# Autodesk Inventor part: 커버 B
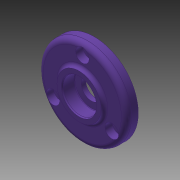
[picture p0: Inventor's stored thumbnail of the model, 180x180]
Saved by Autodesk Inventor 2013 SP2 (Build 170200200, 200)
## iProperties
Created: 2020-04
Part Number: 커버 B
Material: 알루미늄 6061
Document SubType Name: Modeling
Designer: mduedu
Density: 2.71 g/cm^3
Mass: 35.0669 g
Surface Area: 63.5386 cm^2
Volume: 12.9398 cm^3
Author: mduedu
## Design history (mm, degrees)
sketch "스케치1"
  geometry: C1 r 26 at (0, 0); 1 further point
  constraints: 1 centre point, 1 coincident
  dimensions: "d0" = 52 diameter of C1
extrude "돌출1" new body sketch "스케치1" distance "d1" = 7; taper "d2" = 0 deg
sketch "스케치6"
  geometry: C1 r 13 at (0, 0); 1 further point
  constraints: 1 centre point, 1 coincident
  dimensions: "d29" = 26 diameter of C1
extrude "돌출5" join sketch "스케치6" distance "d30" = 2; taper "d31" = 0 deg
fillet "모깎기2" dims "d7" = 3
fillet "모깎기4" dims "d33" = 2
sketch "스케치3" dims "d8" = 40
  geometry: 3 further points
  constraints: 2 vertical alignment, 1 coincident, 2 other
hole "구멍1" sketch "스케치3" at (0, 20) diameter "d9" = 4.5; stored, may be unused: countersink angle "d13" = 90 deg, drill point angle "d15" = 118 deg; dims "d10" = 6, "d11" = 8, "d12" = 4.4, "d14" = 8
sketch "스케치4"
  geometry: C1 r 14 at (0, 0); 1 further point
  constraints: 1 centre point, 1 coincident
  dimensions: "d19" = 28 diameter of C1
extrude "돌출3" join sketch "스케치4" distance "d20" = 4; taper "d21" = 0 deg
sketch "스케치5"
  geometry: C1 r 12 at (0, 0); 1 further point
  constraints: 1 centre point, 1 coincident
  dimensions: "d22" = 24 diameter of C1
extrude "돌출4" cut sketch "스케치5" distance "d23" = 3; taper "d24" = 0 deg
fillet "모깎기3" dims "d25" = 3
chamfer "모따기1" distance "d26" = 0.5; stored, may be unused: second distance "d27" = 2, angle "d28" = 45 deg
sketch "스케치7"
  geometry: 2 further points
  constraints: 1 coincident
hole "구멍2" sketch "스케치7" at (0, 0) diameter "d34" = 14; stored, may be unused: countersink angle "d38" = 90 deg, drill point angle "d40" = 118 deg; dims "d35" = 6, "d36" = 22, "d37" = 7.3, "d39" = 8
fillet "모깎기5" dims "d41" = 0.3
chamfer "모따기2" distance "d42" = 0.7; stored, may be unused: second distance "d43" = 2, angle "d44" = 30 deg
node "솔리드1"
pattern_circular "원형 패턴1" dims angle "d17" = 360 deg
